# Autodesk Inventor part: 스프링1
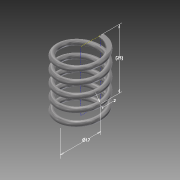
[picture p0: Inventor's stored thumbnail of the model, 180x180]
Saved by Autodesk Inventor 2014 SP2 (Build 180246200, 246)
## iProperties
Created: 2016-03
Part Number: 스프링1
Material: 스테인레스 스틸
Document SubType Name: Modeling
Designer: apexhp001
Density: 8.08 g/cm^3
Appearance: 반연마
Mass: 6.63797 g
Surface Area: 16.7219 cm^2
Volume: 0.821531 cm^3
Author: apexhp001
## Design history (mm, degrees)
sketch "스케치1"
  geometry: L1 (0, 0)-(8.5, 0); L2 (8.5, 0)-(8.5, 20.5); L3 (8.5, 20.5)-(0, 20.5); L4 (0, 20.5)-(0, 0); C1 r 1 at (8.5, 0)
  constraints: 8 end point, 2 parallel, 1 centre point, 1 coincident, 1 horizontal, 1 perpendicular
  dimensions: "d0" = 20.5 distance of L1.end L2.end (derived); "d1" = 17 diameter of L1.end L4; "d2" = 2 diameter of C1
feature "코일1" sketch "스케치1" pitch "d3" = 10; turns "d5" = 5; dims "d4" = 20.5 (= d0), "d6" = 0, angle "d7" = 90 deg, angle "d8" = 90 deg, "d9" = 0, "d10" = 0
sketch "스케치2"
  geometry: L1 (0, 9.5)-(0, 7.5) reference; 1 further point
  constraints: 1 vertical alignment
extrude "돌출1" cut sketch "스케치2" distance "d11" = 10; taper "d12" = 0 deg
node "작업 평면1"
sketch "스케치3"
  geometry: L1 (0, 7.5)-(0, 9.5) reference; 1 further point
  constraints: 1 vertical alignment
extrude "돌출2" cut sketch "스케치3" distance "d14" = 10; taper "d15" = 0 deg
node "솔리드1"
node "절단 모서리 투영1"
node "절단 모서리 투영2"
other parameters: "d13" = 20.5 (= d0)
